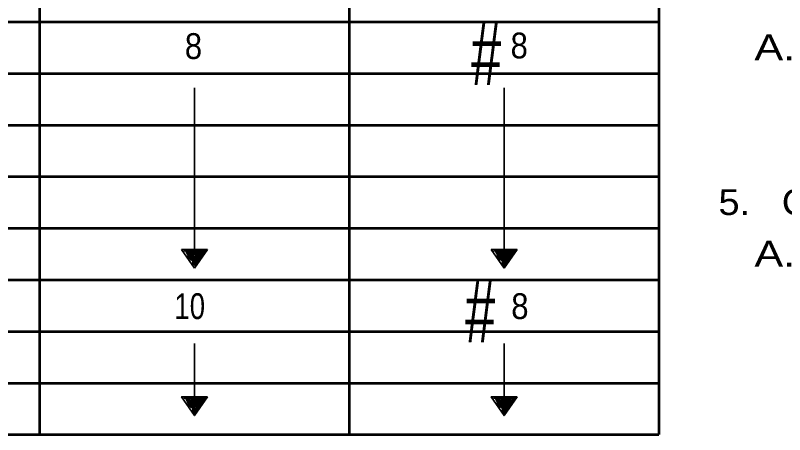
# Model space of a CAD drawing. Extents: x -560 to 120, y 26 to 466.
# Drawn here: x -57.5 to 2.1, y 267.2 to 299.7 of the extents above; entities that cross this region are included whole.
import ezdxf
from ezdxf.enums import TextEntityAlignment as Align

# ---------------------------------------------------------------- set-up
doc = ezdxf.new("R2010")
doc.units = 0
doc.header["$LTSCALE"] = 0.8
doc.layers.add('1', color=7, linetype='Continuous', lineweight=53)

msp = doc.modelspace()

# ---------------------------------------------------------------- linework, layer by layer
at = {"layer": '1'}
for p, q in [((-55.5954, 440.21), (-55.5954, 267.21)), ((-7.5954, 440.21), (-7.5954, 267.21)), ((-31.5954, 431.71), (-31.5954, 267.21)), ((-267.5954, 299.21), (-7.6086, 299.21)), ((-267.5954, 295.21), (-7.6086, 295.21)), ((-267.5954, 291.21), (-7.6086, 291.21)), ((-267.5954, 287.21), (-7.6086, 287.21)), ((-267.5954, 283.21), (-7.6086, 283.21)), ((-267.5954, 279.21), (-7.6086, 279.21)), ((-267.5954, 275.21), (-7.6086, 275.21)), ((-267.5954, 271.21), (-7.6086, 271.21)), ((-267.5954, 267.21), (-7.5954, 267.21))]:
    msp.add_line(p, q, dxfattribs=at)
at = {"layer": '1', "lineweight": 35}
for p, q in [((-43.5954, 294.0946), (-43.5954, 281.5696)), ((-19.5954, 294.0946), (-19.5954, 280.1172)), ((-43.5954, 280.1172), (-44.5954, 281.5696)), ((-44.5954, 281.5696), (-42.5954, 281.5696)), ((-42.5954, 281.5696), (-43.5954, 280.1172)), ((-19.5954, 280.1172), (-20.5954, 281.5696)), ((-20.5954, 281.5696), (-18.5954, 281.5696)), ((-18.5954, 281.5696), (-19.5954, 280.1172)), ((-43.5954, 274.2618), (-43.5954, 268.6897)), ((-19.5954, 274.2618), (-19.5954, 268.6897))]:
    msp.add_line(p, q, dxfattribs=at)
for points in [[(-44.4085, 281.4263), (-44.1026, 281.4603), (-43.6268, 281.3584), (-43.2868, 281.4263), (-43.1509, 281.4263), (-42.9469, 281.4943), (-42.811, 281.4603), (-43.4228, 281.3244), (-43.6947, 281.5623), (-43.6608, 281.3244), (-43.6608, 281.3924), (-43.3548, 281.4943), (-42.9809, 281.4943), (-43.0489, 281.4263), (-43.7627, 281.4603), (-44.0346, 281.4263), (-44.2045, 281.3584), (-44.0686, 281.2564), (-44.0006, 281.1205), (-43.9326, 280.9845), (-43.8987, 280.8826), (-43.7967, 280.7466), (-43.4907, 280.5087), (-43.4907, 280.3048), (-43.5927, 280.5087), (-43.6608, 280.6786), (-43.7967, 280.8486), (-43.9326, 281.0185), (-44.1366, 281.1884), (-44.2725, 281.4263), (-44.1366, 281.2224), (-44.0686, 280.9845), (-43.9666, 280.8486), (-43.8987, 280.7806), (-43.7287, 280.6786), (-43.6268, 280.6107), (-43.5587, 280.4747), (-43.5247, 280.4407), (-43.6268, 280.4747), (-43.7287, 280.6446), (-43.7287, 280.4747), (-43.3548, 280.5767), (-42.845, 281.4603), (-42.811, 281.4603), (-42.845, 281.3244), (-42.9809, 281.0865), (-43.1169, 280.8826), (-43.1509, 280.8826), (-43.2868, 280.6446), (-43.3888, 280.4407), (-43.4907, 280.3048), (-43.5587, 280.3048), (-42.777, 281.4603), (-42.811, 281.3584), (-42.709, 281.4263), (-42.845, 281.2564), (-43.0489, 281.0185), (-43.1509, 280.9505), (-43.2868, 280.7126), (-43.3548, 280.6786), (-43.4567, 280.8146), (-43.5927, 280.8146), (-43.7287, 280.8146), (-43.4907, 280.6107), (-43.5247, 280.7126), (-43.6947, 280.6107), (-43.3548, 281.0525), (-43.4228, 280.9165), (-43.4567, 280.8486), (-43.5927, 280.8486), (-43.7287, 280.9505), (-43.7627, 281.1544), (-43.8307, 281.2224), (-43.8987, 281.2904), (-43.5587, 281.3924), (-43.4228, 281.1884), (-43.3888, 281.2564), (-43.6608, 281.1205), (-43.4907, 281.1544), (-43.2868, 281.2904), (-43.2188, 281.2224), (-43.4567, 281.0185), (-43.4567, 281.2224), (-43.5927, 281.3584), (-43.8987, 281.2564), (-43.9666, 280.8486), (-43.5587, 281.1884), (-43.3888, 281.1544), (-43.2868, 281.2224), (-43.1848, 281.3244), (-43.3208, 280.9845), (-43.3548, 280.7806), (-43.1169, 281.0865), (-43.2868, 281.0525), (-43.0829, 281.3244), (-43.1848, 281.1884), (-43.2188, 281.1544), (-43.4228, 280.9505), (-43.4567, 280.9845), (-43.5247, 281.1205), (-43.5587, 281.2904)], [(-20.4085, 281.4263), (-20.1026, 281.4603), (-19.6267, 281.3584), (-19.2868, 281.4263), (-19.1509, 281.4263), (-18.9469, 281.4943), (-18.811, 281.4603), (-19.4228, 281.3244), (-19.6947, 281.5623), (-19.6608, 281.3244), (-19.6608, 281.3924), (-19.3548, 281.4943), (-18.9809, 281.4943), (-19.0489, 281.4263), (-19.7627, 281.4603), (-20.0346, 281.4263), (-20.2045, 281.3584), (-20.0686, 281.2564), (-20.0006, 281.1205), (-19.9326, 280.9845), (-19.8987, 280.8826), (-19.7967, 280.7466), (-19.4907, 280.5087), (-19.4907, 280.3048), (-19.5927, 280.5087), (-19.6608, 280.6786), (-19.7967, 280.8486), (-19.9326, 281.0185), (-20.1366, 281.1884), (-20.2725, 281.4263), (-20.1366, 281.2224), (-20.0686, 280.9845), (-19.9666, 280.8486), (-19.8987, 280.7806), (-19.7287, 280.6786), (-19.6267, 280.6107), (-19.5587, 280.4747), (-19.5248, 280.4407), (-19.6267, 280.4747), (-19.7287, 280.6446), (-19.7287, 280.4747), (-19.3548, 280.5767), (-18.845, 281.4603), (-18.811, 281.4603), (-18.845, 281.3244), (-18.9809, 281.0865), (-19.1169, 280.8826), (-19.1509, 280.8826), (-19.2868, 280.6446), (-19.3888, 280.4407), (-19.4907, 280.3048), (-19.5587, 280.3048), (-18.777, 281.4603), (-18.811, 281.3584), (-18.709, 281.4263), (-18.845, 281.2564), (-19.0489, 281.0185), (-19.1509, 280.9505), (-19.2868, 280.7126), (-19.3548, 280.6786), (-19.4567, 280.8146), (-19.5927, 280.8146), (-19.7287, 280.8146), (-19.4907, 280.6107), (-19.5248, 280.7126), (-19.6947, 280.6107), (-19.3548, 281.0525), (-19.4228, 280.9165), (-19.4567, 280.8486), (-19.5927, 280.8486), (-19.7287, 280.9505), (-19.7627, 281.1544), (-19.8307, 281.2224), (-19.8987, 281.2904), (-19.5587, 281.3924), (-19.4228, 281.1884), (-19.3888, 281.2564), (-19.6608, 281.1205), (-19.4907, 281.1544), (-19.2868, 281.2904), (-19.2188, 281.2224), (-19.4567, 281.0185), (-19.4567, 281.2224), (-19.5927, 281.3584), (-19.8987, 281.2564), (-19.9666, 280.8486), (-19.5587, 281.1884), (-19.3888, 281.1544), (-19.2868, 281.2224), (-19.1848, 281.3244), (-19.3208, 280.9845), (-19.3548, 280.7806), (-19.1169, 281.0865), (-19.2868, 281.0525), (-19.0829, 281.3244), (-19.1848, 281.1884), (-19.2188, 281.1544), (-19.4228, 280.9505), (-19.4567, 280.9845), (-19.5248, 281.1205), (-19.5587, 281.2904)], [(-43.5587, 281.2904), (-43.7967, 281.1205), (-43.6608, 281.0185), (-44.0686, 281.2564), (-44.0686, 281.3244), (-43.8647, 280.9845), (-43.5247, 281.0185), (-43.6947, 280.9165), (-43.4907, 280.9505), (-43.1848, 281.2564), (-43.0149, 281.2904), (-43.0149, 281.3244), (-43.1169, 281.1205), (-43.4228, 280.7466), (-43.4907, 280.4747), (-44.0006, 281.2904), (-44.0006, 281.4263), (-43.9326, 281.2904), (-44.0006, 280.8826), (-43.6268, 280.6786), (-43.7627, 280.3388), (-43.5927, 280.4067), (-43.7287, 280.8486), (-43.2868, 281.2904), (-43.6608, 281.1884)], [(-19.5587, 281.2904), (-19.7967, 281.1205), (-19.6608, 281.0185), (-20.0686, 281.2564), (-20.0686, 281.3244), (-19.8647, 280.9845), (-19.5248, 281.0185), (-19.6947, 280.9165), (-19.4907, 280.9505), (-19.1848, 281.2564), (-19.0149, 281.2904), (-19.0149, 281.3244), (-19.1169, 281.1205), (-19.4228, 280.7466), (-19.4907, 280.4747), (-20.0006, 281.2904), (-20.0006, 281.4263), (-19.9326, 281.2904), (-20.0006, 280.8826), (-19.6267, 280.6786), (-19.7627, 280.3388), (-19.5927, 280.4067), (-19.7287, 280.8486), (-19.2868, 281.2904), (-19.6608, 281.1884)], [(-44.4085, 269.9988), (-44.1026, 270.0328), (-43.6268, 269.9309), (-43.2868, 269.9988), (-43.1509, 269.9988), (-42.9469, 270.0668), (-42.811, 270.0328), (-43.4228, 269.8969), (-43.6947, 270.1348), (-43.6608, 269.8969), (-43.6608, 269.9649), (-43.3548, 270.0668), (-42.9809, 270.0668), (-43.0489, 269.9988), (-43.7627, 270.0328), (-44.0346, 269.9988), (-44.2045, 269.9309), (-44.0686, 269.8289), (-44.0006, 269.693), (-43.9326, 269.557), (-43.8987, 269.4551), (-43.7967, 269.3191), (-43.4907, 269.0812), (-43.4907, 268.8773), (-43.5927, 269.0812), (-43.6608, 269.2511), (-43.7967, 269.4211), (-43.9326, 269.591), (-44.1366, 269.7609), (-44.2725, 269.9988), (-44.1366, 269.7949), (-44.0686, 269.557), (-43.9666, 269.4211), (-43.8987, 269.3531), (-43.7287, 269.2511), (-43.6268, 269.1832), (-43.5587, 269.0472), (-43.5247, 269.0132), (-43.6268, 269.0472), (-43.7287, 269.2171), (-43.7287, 269.0472), (-43.3548, 269.1492), (-42.845, 270.0328), (-42.811, 270.0328), (-42.845, 269.8969), (-42.9809, 269.659), (-43.1169, 269.4551), (-43.1509, 269.4551), (-43.2868, 269.2171), (-43.3888, 269.0132), (-43.4907, 268.8773), (-43.5587, 268.8773), (-42.777, 270.0328), (-42.811, 269.9309), (-42.709, 269.9988), (-42.845, 269.8289), (-43.0489, 269.591), (-43.1509, 269.523), (-43.2868, 269.2851), (-43.3548, 269.2511), (-43.4567, 269.3871), (-43.5927, 269.3871), (-43.7287, 269.3871), (-43.4907, 269.1832), (-43.5247, 269.2851), (-43.6947, 269.1832), (-43.3548, 269.625), (-43.4228, 269.489), (-43.4567, 269.4211), (-43.5927, 269.4211), (-43.7287, 269.523), (-43.7627, 269.7269), (-43.8307, 269.7949), (-43.8987, 269.8629), (-43.5587, 269.9649), (-43.4228, 269.7609), (-43.3888, 269.8289), (-43.6608, 269.693), (-43.4907, 269.7269), (-43.2868, 269.8629), (-43.2188, 269.7949), (-43.4567, 269.591), (-43.4567, 269.7949), (-43.5927, 269.9309), (-43.8987, 269.8289), (-43.9666, 269.4211), (-43.5587, 269.7609), (-43.3888, 269.7269), (-43.2868, 269.7949), (-43.1848, 269.8969), (-43.3208, 269.557), (-43.3548, 269.3531), (-43.1169, 269.659), (-43.2868, 269.625), (-43.0829, 269.8969), (-43.1848, 269.7609), (-43.2188, 269.7269), (-43.4228, 269.523), (-43.4567, 269.557), (-43.5247, 269.693), (-43.5587, 269.8629)], [(-20.4085, 269.9988), (-20.1026, 270.0328), (-19.6267, 269.9309), (-19.2868, 269.9988), (-19.1509, 269.9988), (-18.9469, 270.0668), (-18.811, 270.0328), (-19.4228, 269.8969), (-19.6947, 270.1348), (-19.6608, 269.8969), (-19.6608, 269.9649), (-19.3548, 270.0668), (-18.9809, 270.0668), (-19.0489, 269.9988), (-19.7627, 270.0328), (-20.0346, 269.9988), (-20.2045, 269.9309), (-20.0686, 269.8289), (-20.0006, 269.693), (-19.9326, 269.557), (-19.8987, 269.4551), (-19.7967, 269.3191), (-19.4907, 269.0812), (-19.4907, 268.8773), (-19.5927, 269.0812), (-19.6608, 269.2511), (-19.7967, 269.4211), (-19.9326, 269.591), (-20.1366, 269.7609), (-20.2725, 269.9988), (-20.1366, 269.7949), (-20.0686, 269.557), (-19.9666, 269.4211), (-19.8987, 269.3531), (-19.7287, 269.2511), (-19.6267, 269.1832), (-19.5587, 269.0472), (-19.5248, 269.0132), (-19.6267, 269.0472), (-19.7287, 269.2171), (-19.7287, 269.0472), (-19.3548, 269.1492), (-18.845, 270.0328), (-18.811, 270.0328), (-18.845, 269.8969), (-18.9809, 269.659), (-19.1169, 269.4551), (-19.1509, 269.4551), (-19.2868, 269.2171), (-19.3888, 269.0132), (-19.4907, 268.8773), (-19.5587, 268.8773), (-18.777, 270.0328), (-18.811, 269.9309), (-18.709, 269.9988), (-18.845, 269.8289), (-19.0489, 269.591), (-19.1509, 269.523), (-19.2868, 269.2851), (-19.3548, 269.2511), (-19.4567, 269.3871), (-19.5927, 269.3871), (-19.7287, 269.3871), (-19.4907, 269.1832), (-19.5248, 269.2851), (-19.6947, 269.1832), (-19.3548, 269.625), (-19.4228, 269.489), (-19.4567, 269.4211), (-19.5927, 269.4211), (-19.7287, 269.523), (-19.7627, 269.7269), (-19.8307, 269.7949), (-19.8987, 269.8629), (-19.5587, 269.9649), (-19.4228, 269.7609), (-19.3888, 269.8289), (-19.6608, 269.693), (-19.4907, 269.7269), (-19.2868, 269.8629), (-19.2188, 269.7949), (-19.4567, 269.591), (-19.4567, 269.7949), (-19.5927, 269.9309), (-19.8987, 269.8289), (-19.9666, 269.4211), (-19.5587, 269.7609), (-19.3888, 269.7269), (-19.2868, 269.7949), (-19.1848, 269.8969), (-19.3208, 269.557), (-19.3548, 269.3531), (-19.1169, 269.659), (-19.2868, 269.625), (-19.0829, 269.8969), (-19.1848, 269.7609), (-19.2188, 269.7269), (-19.4228, 269.523), (-19.4567, 269.557), (-19.5248, 269.693), (-19.5587, 269.8629)], [(-43.5587, 269.8629), (-43.7967, 269.693), (-43.6608, 269.591), (-44.0686, 269.8289), (-44.0686, 269.8969), (-43.8647, 269.557), (-43.5247, 269.591), (-43.6947, 269.489), (-43.4907, 269.523), (-43.1848, 269.8289), (-43.0149, 269.8629), (-43.0149, 269.8969), (-43.1169, 269.693), (-43.4228, 269.3191), (-43.4907, 269.0472), (-44.0006, 269.8629), (-44.0006, 269.9988), (-43.9326, 269.8629), (-44.0006, 269.4551), (-43.6268, 269.2511), (-43.7627, 268.9112), (-43.5927, 268.9792), (-43.7287, 269.4211), (-43.2868, 269.8629), (-43.6608, 269.7609)], [(-19.5587, 269.8629), (-19.7967, 269.693), (-19.6608, 269.591), (-20.0686, 269.8289), (-20.0686, 269.8969), (-19.8647, 269.557), (-19.5248, 269.591), (-19.6947, 269.489), (-19.4907, 269.523), (-19.1848, 269.8289), (-19.0149, 269.8629), (-19.0149, 269.8969), (-19.1169, 269.693), (-19.4228, 269.3191), (-19.4907, 269.0472), (-20.0006, 269.8629), (-20.0006, 269.9988), (-19.9326, 269.8629), (-20.0006, 269.4551), (-19.6267, 269.2511), (-19.7627, 268.9112), (-19.5927, 268.9792), (-19.7287, 269.4211), (-19.2868, 269.8629), (-19.6608, 269.7609)]]:
    msp.add_lwpolyline(points, dxfattribs=at)
for points in [[(-42.5954, 270.1421), (-43.5954, 268.6897), (-44.5954, 270.1421)], [(-18.5954, 270.1421), (-19.5954, 268.6897), (-20.5954, 270.1421)]]:
    msp.add_lwpolyline(points, close=True, dxfattribs=at)

# ---------------------------------------------------------------- texts
at = {"layer": '1'}
for s, height, width, p in [('#', 4.8, 0.65, (-20.9826, 294.3187)), ('8', 2, 0.9, (-43.6735, 296.3266)), ('8', 2, 0.9, (-18.4242, 296.3718)), ('#', 4.8, 0.65, (-21.4477, 274.3641)), ('10', 2, 0.8, (-43.964, 276.1687)), ('8', 2, 0.9, (-18.3701, 276.1686))]:
    msp.add_text(s, height=height, dxfattribs=dict(at, width=width)).set_placement(p, align=Align.CENTER)
for s, width, p in [('   A.   NO FORMS MAY EXTEND TO A DEPTH GREATER THAN 12"', 1.25, (-2.9781, 296.233)), ('5.   CONDUIT:', 1.1, (-2.9781, 284.233)), ('   A.   THE RADIUS (R) OF THE CURVE OF THE INNER EDGE OF', 1.25, (-2.9781, 280.233))]:
    msp.add_text(s, height=2, dxfattribs=dict(at, width=width)).set_placement(p)

doc.saveas('drawing.dxf')
